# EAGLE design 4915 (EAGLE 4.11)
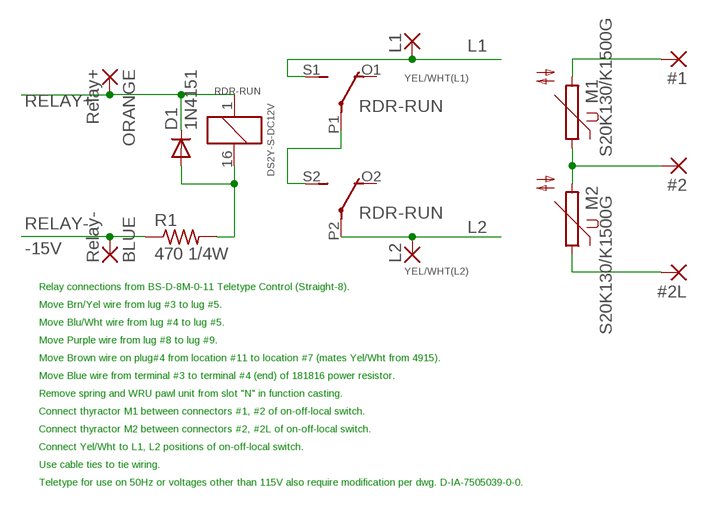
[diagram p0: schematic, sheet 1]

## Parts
#1  2,15/1,0  [2,15/1,0]
#2  2,15/1,0  [2,15/1,0]
#2L  2,15/1,0  [2,15/1,0]
BLUE  Relay-  2,15/1,0  [2,15/1,0]
D1  1N4151  1N4148  [DO35-10]
M1  S20K130/K1500G  S10K40  [S10K40]
M2  S20K130/K1500G  S10K40  [S10K40]
ORANGE  Relay+  2,15/1,0  [2,15/1,0]
R1  470 1/4W  R-US_0309/12  [0309/12]
RDR-RUN  DS2Y-S-DC12V  351  [351]
YEL/WHT(L1)  L1  2,15/1,0  [2,15/1,0]
YEL/WHT(L2)  L2  2,15/1,0  [2,15/1,0]

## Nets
-15V: BLUE.1(P) R1.1
L1: RDR-RUN.S1(2:S) YEL/WHT(L1).1(P)
L2: RDR-RUN.P2(3:P) YEL/WHT(L2).1(P)
N$1: D1.A R1.2 RDR-RUN.16
N$2: RDR-RUN.P1(2:P) RDR-RUN.S2(3:S)
N$3: #1.1(P) M1.2
N$4: #2.1(P) M1.1 M2.2
N$5: #2L.1(P) M2.1
RELAY+: D1.C ORANGE.1(P) RDR-RUN.1
Unconnected: RDR-RUN.O1(2:O) RDR-RUN.O2(3:O)

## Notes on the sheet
- RELAY-
- Relay connections from BS-D-8M-0-11 Teletype Control (Straight-8).
- Move Brn/Yel wire from lug #3 to lug #5.
- Move Blu/Wht wire from lug #4 to lug #5.
- Move Purple wire from lug #8 to lug #9.
- Move Brown wire on plug#4 from location #11 to location #7 (mates Yel/Wht from 4915).
- Move Blue wire from terminal #3 to terminal #4 (end) of 181816 power resistor.
- Remove spring and WRU pawl unit from slot "N" in function casting.
- Connect thyractor M1 between connectors #1, #2 of on-off-local switch.
- Connect thyractor M2 between connectors #2, #2L of on-off-local switch.
- Connect Yel/Wht to L1, L2 positions of on-off-local switch.
- Use cable ties to tie wiring.
- Teletype for use on 50Hz or voltages other than 115V also require modification per dwg. D-IA-7505039-0-0.

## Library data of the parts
#1 #2 #2L BLUE ORANGE YEL/WHT(L1) YEL/WHT(L2) = wirepad:2,15/1,0: THROUGH-HOLE PAD
D1 = diode:1N4148: DIODE
M1 M2 = varistor:S10K40: VARISTOR
R1 = rcl:R-US_: RESISTOR, American symbol
RDR-RUN = relay:351: RELAY 2 x switch, Omron

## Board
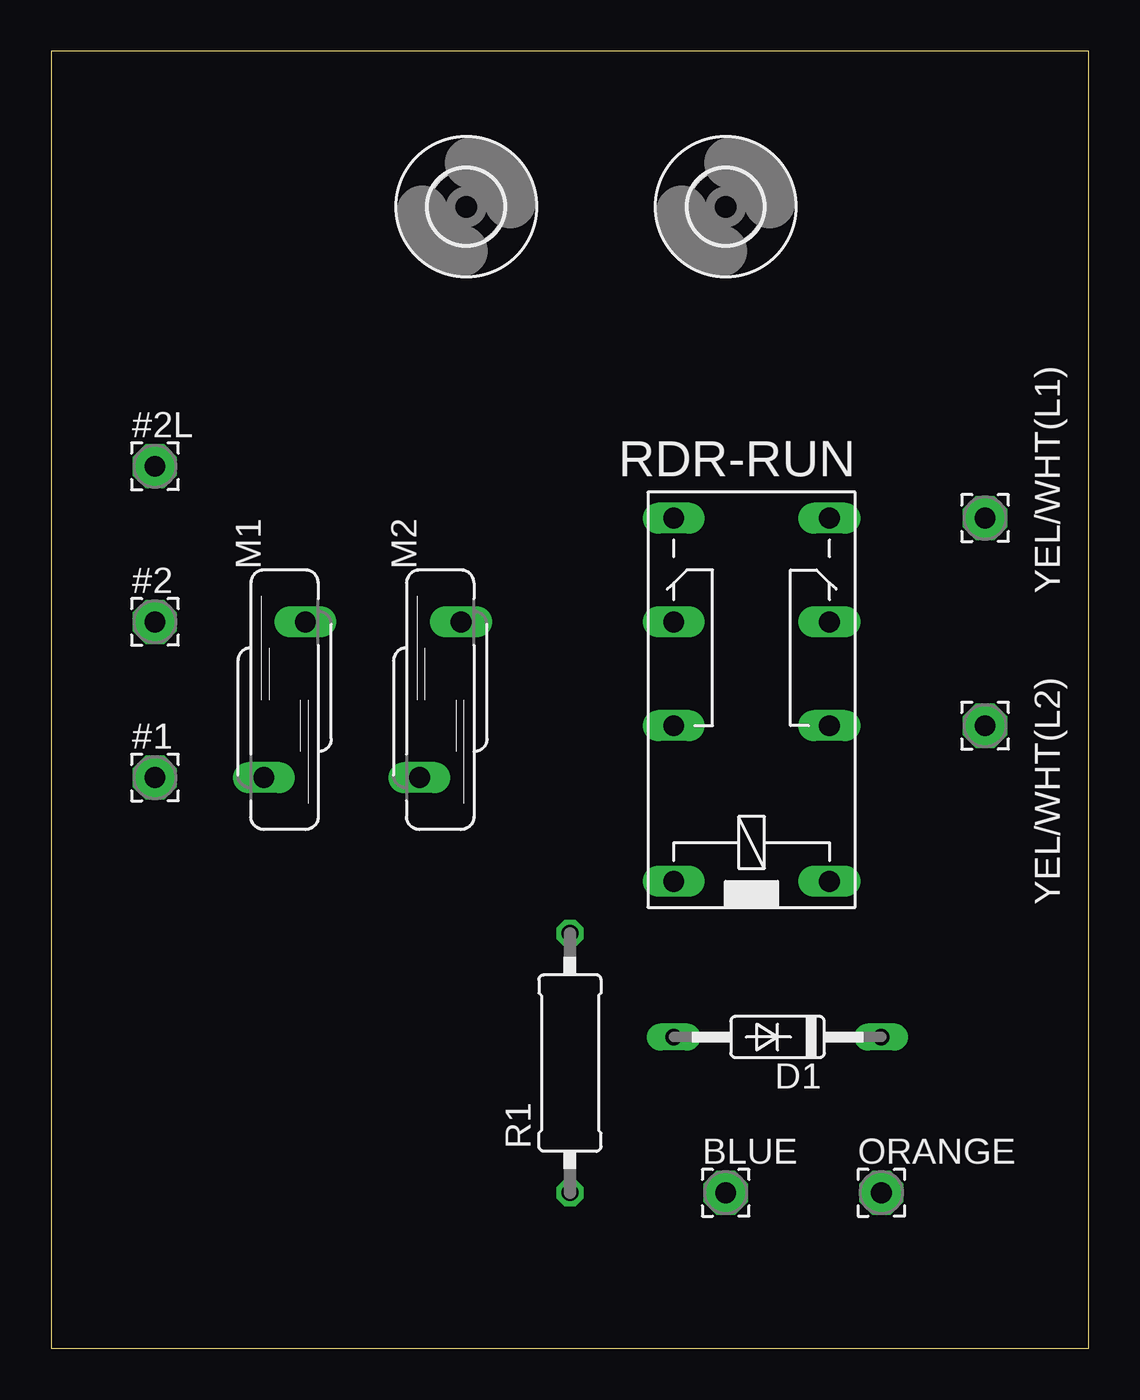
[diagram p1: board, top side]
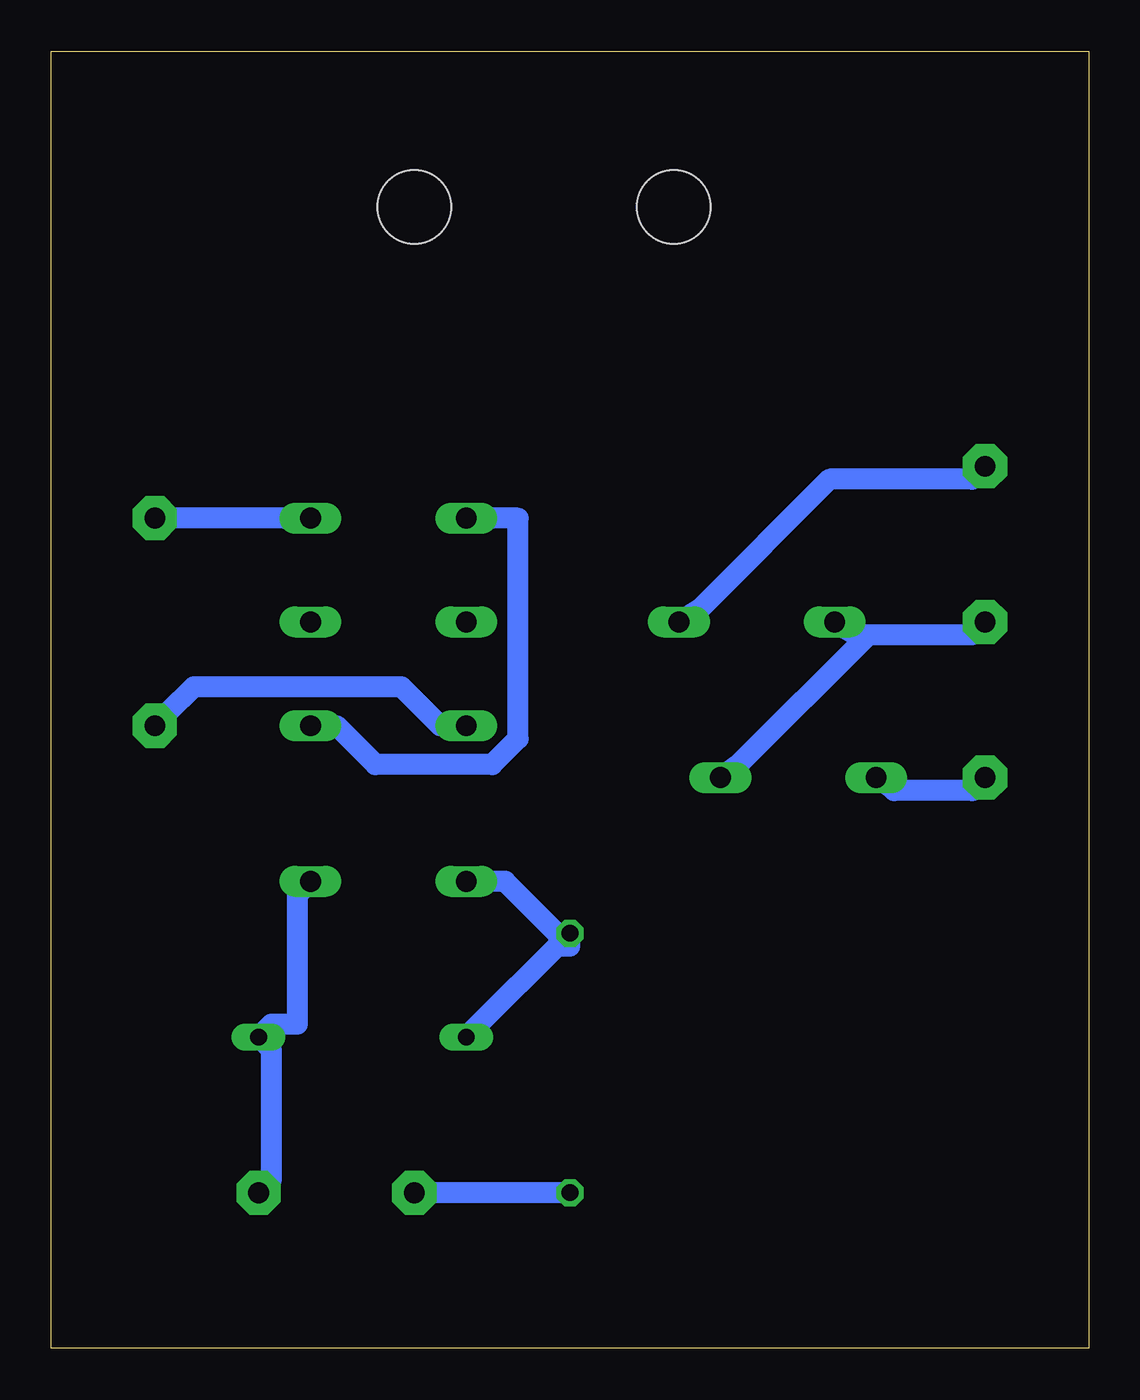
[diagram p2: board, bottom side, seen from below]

Size 50.8 x 63.5 mm. Coordinates in mm from the lower left corner, seen from the top.
Outline: 0,0 50.8,0 50.8,63.5 0,63.5 0,0
Copper layers (1*16): Top 0.035mm / dielectric 1.5mm / Bottom 0.035mm
Design rules "40mils": minimum track width 40mil, minimum drill 24mil, track to track 20mil, track to pad 10mil, pad to pad 10mil, via to via 10mil, smd to smd 10mil, copper to edge 25mil, drill to drill 10mil, minimum pad ring 10mil, minimum via ring 8mil, stop-mask expansion 0mil, vias tented up to drill 0mil, thermal gap 10mil

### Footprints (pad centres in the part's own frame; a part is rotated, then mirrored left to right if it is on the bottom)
2,15/1,0 = drill 1.016 pad 2.159 octagon: 1 0,0
DO35-10 = drill 0.813 long: A 5.08,0; C -5.08,0
S10K40 = drill 1.016 long: 1 -1.016,-3.81; 2 1.016,3.81
0309/12 = drill 0.813 octagon: 1 -6.35,0; 2 6.35,0
351 = drill 1.016 long: 1 -3.81,-3.81; 16 -3.81,3.81; O1 8.89,-3.81; O2 8.89,3.81; P1 3.81,-3.81; P2 3.81,3.81; S1 13.97,-3.81; S2 13.97,3.81
3,6 = hole 3.6: 0,0

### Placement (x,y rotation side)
#1  5.08,27.94 0 top
#2  5.08,35.56 0 top
#2L  5.08,43.18 0 top
BLUE  33.02,7.62 0 top
D1  35.56,15.24 180 top
M1  11.43,31.75 180 top
M2  19.05,31.75 180 top
ORANGE  40.64,7.62 0 top
R1  25.4,13.97 90 top
RDR-RUN  34.29,26.67 90 top
U$1  [3,6]  20.32,55.88 0 top
U$2  [3,6]  33.02,55.88 0 top
YEL/WHT(L1)  45.72,40.64 0 top
YEL/WHT(L2)  45.72,30.48 0 top

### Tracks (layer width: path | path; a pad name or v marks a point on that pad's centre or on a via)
-15V
  Bottom 1.016: R1.1 26.04,7.62 32.38,7.62 BLUE.1
L1
  Bottom 1.016: RDR-RUN.S1 39.37,40.64 45.09,40.64 YEL/WHT(L1).1
L2
  Bottom 1.016: RDR-RUN.P2 31.75,30.48 33.66,32.38 43.81,32.38 45.09,31.11 YEL/WHT(L2).1
N$1
  Bottom 1.016: RDR-RUN.16 29.21,22.86 28.57,22.86 26.04,20.32 R1.2 25.4,19.68 26.04,19.68 29.84,15.88 D1.A
N$2
  Bottom 1.016: RDR-RUN.P1 36.83,30.48 34.92,28.57 29.21,28.57 27.94,29.84 27.94,40.64 29.21,40.64 RDR-RUN.S2
N$3
  Bottom 1.016: M1.2 9.53,27.3 5.71,27.3 #1.1
N$4
  Bottom 1.016: 10.79,34.92 5.71,34.92 #2.1 | 10.79,34.92 11.43,34.92 M1.1 | 10.79,34.92 17.14,28.57 M2.2
N$5
  Bottom 1.016: M2.1 19.05,36.2 12.7,42.55 5.71,42.55 #2L.1
RELAY+
  Bottom 1.016: ORANGE.1 40.01,8.26 40.01,14.61 D1.C 40.01,15.88 38.73,15.88 38.73,22.23 RDR-RUN.1

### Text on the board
tValues: Also: | WHT - 6 | BLK - 7 | RED - 4 | GRN - 3 | Relay- | Relay+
